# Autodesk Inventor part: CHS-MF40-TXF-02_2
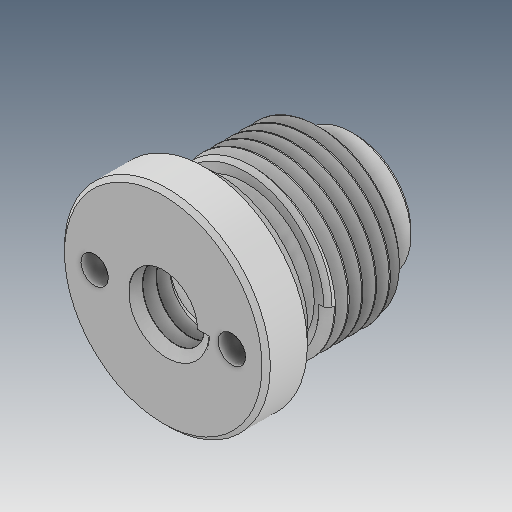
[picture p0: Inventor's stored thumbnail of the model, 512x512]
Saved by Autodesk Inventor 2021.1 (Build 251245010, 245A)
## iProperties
Created: 2019-05
Part Number: CHS-MF40-TXF-02_2
Material: Ogólny
Document SubType Name: Modeling
Designer: user
Density: 1 g/cm^3
Appearance: Domyślna
Author: user
Revision Number: ÈÎºÎ
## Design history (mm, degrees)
feature "ÊäÈë1"
node "Bryła1"
